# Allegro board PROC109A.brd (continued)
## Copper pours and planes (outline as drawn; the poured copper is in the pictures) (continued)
DGND on TOP: 50.8,-28.4 50.68,-28.52 50.68,-28.9 50.5,-29.07 49.77,-29.07 49.76,-29.08 46.97,-29.08 46.59,-28.7 46.59,-27.81 46.33,-27.56 45.83,-27.56 45.7,-27.69 45.7,-29.46 45.06,-29.46 44.68,-29.84 44.68,-30.86 44.57,-30.98 39.63,-30.98 39.37,-31.24 39.37,-33.91 39.62,-34.16 42.42,-34.16 42.86,-33.72 42.86,-31.94 43.31,-31.5 44.35,-31.5 44.35,-33.83 44.56,-34.04 45.49,-34.04 46.2,-33.32 53.39,-33.32 53.8,-32.92 53.8,-28.88 53.31,-28.4
DGND on TOP: 4.85,-54.79 4.85,-55.41 5.56,-56.12 7.63,-56.12 8.36,-56.85 10.19,-56.85 10.46,-56.57 10.46,-54.88 10.17,-54.58 5.05,-54.58
DGND on TOP: 74.68,-34.16 74.68,-34.71 75.19,-35.22 75.53,-35.22 76.48,-36.17 76.48,-36.53 76.65,-36.71 76.87,-36.71 76.96,-36.62 76.96,-34.88 76.24,-34.16
DGND on BOTTOM: 37.67,-36.4 37.92,-36.65 37.92,-37.29 37.67,-37.54 35.76,-37.54 35.66,-37.44 35.66,-36.47 35.74,-36.4
DGND on BOTTOM: 7.32,-56.64 10.72,-56.64 10.98,-56.38 10.98,-54.86 10.76,-54.64 7.34,-54.64 7.04,-54.94 7.04,-56.36
DGND on BOTTOM: 73.63,-40.61 75.9,-40.61 76.02,-40.49 76.02,-40.05 75.82,-39.85 73.62,-39.85 73.56,-39.91 73.56,-40.54
DGND on BOTTOM: 81.98,-47.97 83.24,-47.97 83.27,-48.01 83.27,-51.54 83.64,-51.91 83.64,-52.22 83.49,-52.37 81.89,-52.37 81.79,-52.27 81.79,-48.16
DGND on BOTTOM: 86.41,-49.79 86.32,-49.7 86.32,-48.44 86.58,-48.18 87.99,-48.18 88.14,-48.34 88.14,-49.64 87.99,-49.79
DGND on BOTTOM: 89.08,-45.69 89.49,-46.11 90.74,-46.11 90.86,-46.22 90.86,-46.61 90.7,-46.76 87.05,-46.76 86.9,-46.61 86.9,-45.83 87.03,-45.69
DGND on BOTTOM: 83.69,-42.11 83.69,-42.98 83.79,-43.08 84.96,-43.08 85.24,-42.8 85.24,-42.62 85.12,-42.49 85.12,-41.81 85.04,-41.73 84.73,-41.73 84.61,-41.86 84.61,-41.99 84.53,-42.06 83.74,-42.06
DGND on BOTTOM: 31.11,-60.93 33.78,-60.93 33.96,-60.76 33.96,-58.37 34.39,-57.94 38.33,-57.94 38.46,-57.81 38.46,-56.31 38.35,-56.21 36.37,-56.21 35.86,-55.7 35.86,-53.87 35.7,-53.71 31.63,-53.71 30.35,-52.43 24.76,-52.43 24.26,-52.93 24.26,-58.13 24.65,-58.52 28.7,-58.52
DGND on BOTTOM: 184.68,-10.16 184.68,-66.57 1.09,-66.57 1.09,-10.16 ; 123 cut-outs
DGND on BOTTOM: 86.12,-38.85 86.76,-38.21 89.05,-38.21 89.36,-37.9 89.36,-35.64 89.13,-35.41 86.13,-35.41 85.67,-35.86 85.67,-38.8 85.73,-38.85
DGND on BOTTOM: 78.03,-48.24 78.12,-48.34 78.12,-50.77 78.29,-50.94 78.29,-52.37 78.23,-52.43 76.45,-52.43 76.17,-52.15 76.17,-49.38 77.32,-48.24
DGND on BOTTOM: 81.74,-30.86 81.74,-32.49 81.79,-32.54 81.79,-34.26 82.19,-34.67 82.19,-36.01 80.9,-37.31 80.9,-37.67 80.98,-37.74 82.07,-37.74 82.19,-37.87 82.19,-38.46 82.37,-38.63 83.26,-38.63 83.36,-38.53 83.36,-36.86 83.19,-36.68 83.19,-35.63 82.96,-35.4 82.96,-32.89 83.79,-32.05 83.79,-31.04 83.52,-30.76 81.83,-30.76
DGND on BOTTOM: 78.55,-37.08 78.55,-34.81 78.44,-34.7 73.13,-34.7 72.85,-34.98 72.85,-37.04 72.92,-37.12 73.46,-37.12 73.71,-37.37 75.01,-37.37 75.31,-37.07 77.72,-37.07 77.88,-37.22 77.88,-39.57 78,-39.7 78.23,-39.7 78.36,-39.57 78.36,-37.26
DGND on BOTTOM: 86.33,-40.34 89.03,-40.34 89.23,-40.54 89.63,-40.54 89.74,-40.64 89.74,-41.1 89.73,-41.11 89.73,-41.72 89.48,-41.96 88.75,-41.96 88.44,-41.66 88.44,-41.35 88.29,-41.2 86.64,-41.2 86.31,-41.53 86.26,-41.53 85.78,-41.05 85.78,-40.89
DGND on BOTTOM: 11.39,-41.23 12.43,-41.23 12.84,-41.65 12.84,-43.69 12.97,-43.82 14.61,-43.82 14.78,-43.65 14.78,-43.28 14.66,-43.15 13.5,-43.15 13.39,-43.03 13.39,-40.69 13.21,-40.51 11.44,-40.51 11.24,-40.71 11.24,-41.09
DGND on BOTTOM: 127.95,-38.23 129.41,-38.23 129.67,-37.97 129.67,-34.22 129.48,-34.04 127.66,-34.04 127.52,-34.18 127.52,-34.76 127.15,-35.13 127.15,-35.51 127.75,-36.11 127.75,-38.03
DGND on L02_GND1: 184.22,-10.19 184.34,-12.55 184.34,-20.18 179.84,-20.18 179.84,-19.68 177.98,-17.81 174.08,-17.81 173.85,-18.05 173.85,-32.06 171.1,-34.82 168.29,-34.82 167.93,-35.17 167.93,-37.26 168.31,-37.64 176.06,-37.64 178.47,-35.23 184.33,-35.23 184.33,-41.81 180.27,-41.81 180.04,-41.58 180.04,-40.45 179.28,-39.69 174.67,-39.69 173.86,-40.5 173.86,-53.4 170.1,-57.16 170.1,-59.41 173.01,-59.41 173.93,-60.32 175.85,-60.32 177.9,-58.27 177.9,-57.47 178.42,-56.95 183.91,-56.95 183.91,-59.22 180.97,-62.15 180.97,-66.46 9.95,-66.46 8.84,-65.34 8.84,-58.3 6.16,-55.63 4.93,-55.63 4.37,-55.07 4.37,-52.6 4.95,-52.02 6.08,-52.02 7.16,-50.94 7.16,-48.97 6.91,-48.72 1.36,-48.72 1.11,-48.46 1.11,-10.19 1.11,-10.98 1.18,-11.08 1.29,-11.04 1.62,-10.66 2,-10.33 2.04,-10.27 2.03,-10.19
DGND on L03_SIG1: 184.68,-10.19 184.68,-66.57 1.09,-66.57 1.09,-10.19 ; 139 cut-outs
DGND on L05_GND2: 27.77,-66.53 27.48,-66.24 27.48,-59.13 27.23,-58.88 24.43,-58.88 23.63,-58.07 22.19,-58.07 20.75,-59.51 15.67,-59.51 15.39,-59.23 15.39,-58.72 15.04,-58.37 8.9,-58.37 6.74,-56.21 5.68,-56.21 4.11,-54.64 4.11,-52.27 4.37,-52.02 6.65,-52.02 7.16,-51.51 7.16,-48.97 6.91,-48.72 1.36,-48.72 1.15,-48.51 1.15,-11.35 2.23,-10.27 184.33,-10.27 184.33,-21.54 180.72,-21.54 179.87,-20.68 179.87,-19.7 177.98,-17.81 174.08,-17.81 173.85,-18.05 173.85,-32.06 171.1,-34.82 168.29,-34.82 167.93,-35.17 167.93,-37.26 168.31,-37.64 176.06,-37.64 178.51,-35.18 184.33,-35.18 184.33,-41.81 180.04,-41.81 180.04,-40.45 179.28,-39.69 174.67,-39.69 173.86,-40.5 173.86,-53.4 170.1,-57.16 170.1,-59.41 173.01,-59.41 173.93,-60.32 175.85,-60.32 177.9,-58.27 177.9,-57.47 178.47,-56.9 184.29,-56.9 184.29,-59.98 180.85,-63.42 180.85,-66.53 ; 2 cut-outs
VBUS_TYPEC on TOP: 19.64,-56.18 19.32,-55.86 19.32,-54.89 19.11,-54.68 17.66,-54.68 17.27,-55.07 17.27,-56 17.19,-56.08 15.31,-56.08 15.11,-55.88 15.11,-53.34 15.11,-53.34 15.11,-48.81 15.58,-48.34 21.03,-48.34 21.63,-48.95 21.63,-52.48 21.48,-52.63 21.48,-53.87 20.99,-54.37 20.99,-55.49 20.3,-56.18
VBUS_TYPEC on BOTTOM: 17.31,-54.23 17.31,-55.11 17.7,-55.5 19.3,-55.5 19.42,-55.38 19.42,-50.58 19.71,-50.29 20.9,-50.29 22.66,-52.05 22.66,-56.97 21.06,-58.57 15.39,-58.57 14.1,-57.28 14.1,-54.36 14.48,-53.97 17.05,-53.97
VBUS_TYPEC on L03_SIG1: 15.11,-52.71 15.12,-52.71 15.12,-49.86 16.63,-48.34 21.44,-48.34 21.83,-48.73 21.83,-55.78 21.43,-56.18 20.3,-56.18 20.3,-56.18 15.46,-56.18 15.11,-55.83
VBUS_XDS_USB on TOP: 4.8,-51.89 4.8,-52.43 4.93,-52.55 6.55,-52.55 7.51,-51.59 10.18,-51.59 10.36,-51.41 10.36,-50.6 10.08,-50.32 7.09,-50.32 6.39,-51.02 5.68,-51.02
VBUS_XDS_USB on BOTTOM: 12.21,-42.32 12.21,-41.91 12.09,-41.78 11.4,-41.78 11.3,-41.88 10.54,-41.88 10.44,-41.78 10.44,-40.59 10.31,-40.46 9.04,-40.46 8.91,-40.59 8.91,-42.39 8.89,-42.41 8.89,-44.23 10.57,-45.91 10.57,-49 9.17,-50.39 7.62,-50.39 7.37,-50.65 7.37,-51.46 7.55,-51.65 9.95,-51.65 11.95,-49.65 11.95,-45.56 9.7,-43.3 9.7,-42.87 9.99,-42.57 11.12,-42.57 11.38,-42.32
VCC3V3_TA on TOP: 5.34,-32.38 5.34,-31.89 5.84,-31.39 5.84,-30.77 5.63,-30.56 4.01,-30.56 3.53,-31.04 3.53,-32.89 3.72,-33.07 5.13,-33.07 5.49,-33.43 8.05,-33.43 8.26,-33.22 8.26,-32.89 8.05,-32.69 5.65,-32.69
VCC3V3_TA on TOP: 10.03,-19.28 11.25,-19.28 11.51,-19.53 11.51,-27.51 11.25,-27.76 10.03,-27.76 9.78,-27.51 9.78,-19.53
VCC3V3_TA on TOP: 29.69,-20.48 29.69,-21.92 29.16,-22.45 28.4,-22.45 28.19,-22.66 28.19,-23.29 28.27,-23.37 29.83,-23.37 30.14,-23.06 30.1,-23.06 30.46,-22.7 30.46,-22.57 30.56,-22.48 30.56,-21.76 31.32,-21 31.32,-20.52 31.16,-20.36 29.82,-20.36
VCC3V3_TA on TOP: 25.98,-22.61 25.98,-32.23 26.19,-32.44 26.59,-32.44 26.72,-32.31 26.72,-22.54 26.7,-22.52 26.07,-22.52
VCC3V3_TA on BOTTOM: 11.68,-19.47 11.68,-26.61 11.73,-26.66 12.4,-26.66 12.71,-26.35 12.71,-19.77 12.36,-19.42 11.73,-19.42
VCC3V3_TA on BOTTOM: 22.23,-20.19 22.23,-21.51 22.38,-21.67 22.96,-21.67 23.06,-21.56 23.06,-20.78 23.35,-20.49 24.69,-20.49 24.73,-20.45 24.73,-19.89 24.69,-19.85 23.08,-19.85 22.83,-20.09 22.33,-20.09
VCC3V3_TA on BOTTOM: 7.24,-48.89 7,-48.65 7,-46.98 6.38,-46.35 6.38,-44.58 6.17,-44.37 6.17,-40.76 5.31,-39.9 5.31,-38.79 5.56,-38.53 7.98,-38.53 8.13,-38.68 8.13,-40.87 8.13,-43.7 7.29,-44.53 7.29,-45.92 7.95,-46.58 9.44,-46.58 9.87,-47.02 9.87,-48.83 9.8,-48.89
VCC3V3_TA on L03_SIG1: 3.05,-28.9 3.05,-40.94 4.09,-41.99 6.71,-41.99 7.72,-40.97 7.72,-39.22 6.02,-37.52 6.02,-30.68 7.19,-29.51 7.57,-29.9 15.6,-29.9 17.46,-28.04 25.49,-28.04 27.15,-26.38 29.4,-26.38 30.35,-25.43 30.35,-21.36 28.52,-19.53 23.79,-19.53 20.6,-22.72 13.07,-22.72 12.4,-22.05 12.4,-19.35 11.89,-18.85 10.68,-18.85 6.83,-22.69 6.83,-25.11 ; 3 cut-outs
VCC3V3_XDS on TOP: 18.08,-36.8 17.5,-36.22 17.5,-28.21 18.04,-27.67 24.03,-27.67 24.03,-28.25 24.26,-28.25 24.67,-28.65 24.81,-28.65 24.81,-28.23 26.05,-28.23 26.05,-27.98 24.81,-27.98 24.81,-27.67 37.75,-27.67 38.35,-28.28 38.35,-36.55 38.1,-36.8 ; 4 cut-outs
VCC3V3_XDS on TOP: 14.17,-40 14.17,-43.23 15.65,-44.7 15.65,-46.66 15.7,-46.72 23.3,-46.72 24.12,-47.53 29.02,-47.53 29.71,-48.23 33.25,-48.23 35.64,-45.85 38.53,-45.85 39.5,-44.88 39.5,-39.85 37.97,-38.33 22.11,-38.33 20.43,-40 ; 3 cut-outs
VCC3V3_XDS on BOTTOM: 14.02,-42.2 14.66,-42.2 15.01,-42.54 16.51,-42.54 16.6,-42.63 17.24,-42.63 17.36,-42.51 17.36,-41.98 17.27,-41.88 16.22,-41.88 16.13,-41.79 16.13,-40 16.01,-39.88 14.1,-39.88 13.9,-40.07 13.9,-42.08
VCC3V3_XDS on BOTTOM: 35.8,-34.24 36.73,-34.24 36.91,-34.42 36.91,-35.48 36.65,-35.74 35.78,-35.74 35.66,-35.61 35.66,-34.37
VCC3V3_XDS on BOTTOM: 36.5,-44.29 36.34,-44.45 35.86,-44.45 35.53,-44.12 35.53,-41.83 35.71,-41.66 36.32,-41.66 36.5,-41.83
VCC3V3_XDS on BOTTOM: 25.16,-47.76 26.22,-47.76 26.42,-47.96 26.42,-48.51 26.16,-48.77 25.18,-48.77 25.04,-48.62 25.04,-47.89
VCC3V3_XDS on L03_SIG1: 13.64,-40.69 13.64,-45.54 15.19,-47.09 20.42,-47.09 20.83,-46.69 22.66,-46.69 23.62,-47.65 23.62,-52.38 26.34,-55.1 35.99,-55.1 36.49,-55.59 39.1,-55.59 40.17,-54.52 59.02,-54.52 59.34,-54.2 59.34,-50.4 58.96,-50.02 40.01,-50.02 38.38,-48.39 38.38,-41.96 38.23,-41.81 38.23,-35.38 36.93,-34.09 34.06,-34.09 33.13,-35.01 24.17,-35.01 21.39,-37.8 16.54,-37.8 ; 1 cut-out
VDD_1V1 on BOTTOM: 124.71,-44.25 124.71,-48.69 124.97,-48.95 126.53,-48.95 127.12,-48.35 127.12,-47.11 126.51,-46.5 126.51,-45.69 126.87,-45.33 126.87,-44.84 126.76,-44.73 126.09,-44.73 125.6,-44.25
VDD_1V1 on L04_PWR1: 136.5,-51.16 136.93,-51.6 139.03,-51.6 139.51,-51.12 139.51,-47.39 139.9,-46.99 144.76,-46.99 145.1,-46.65 145.1,-42.48 144.53,-41.91 139.36,-41.91 138.64,-41.19 138.64,-38.63 141.78,-35.49 141.78,-32.86 142.43,-32.22 144.39,-32.22 145.1,-31.5 145.1,-26.82 144.31,-26.03 133.76,-26.03 133.06,-26.73 133.06,-27.67 136.83,-31.44 136.83,-34.43 132.62,-38.64 125.6,-38.64 124.87,-39.37 124.87,-49.01 125.21,-49.35 130.57,-49.35 131.39,-48.53 131.39,-46.64 131.94,-46.1 135.8,-46.1 136.5,-46.8
VDD_1V8 on TOP: 66.55,-24.24 66.27,-24.51 65.19,-24.51 65.18,-24.5 64.2,-24.5 63.93,-24.23 63.93,-23.09 63.63,-22.78 63.12,-22.78 62.76,-22.43 62.76,-21.03 62.96,-20.83 66.32,-20.83 66.55,-21.06
VDD_1V8 on BOTTOM: 64.49,-21.86 64.49,-23.54 68.24,-27.29 71.29,-27.29 74.65,-30.65 74.65,-33.78 74.92,-34.05 78.49,-34.05 78.49,-32.06 78.23,-31.8 78.23,-30.91 68.85,-21.52 64.83,-21.52
VDD_1V8 on BOTTOM: 91.87,-41.4 93.57,-41.4 93.83,-41.66 93.83,-46.63 93.52,-46.94 91.62,-46.94 91.37,-46.69 91.37,-43.85 91.74,-43.48 91.74,-41.54
VDD_1V8 on BOTTOM: 68.12,-42.88 69.52,-42.88 69.77,-43.13 69.77,-49.48 69.45,-49.81 68.82,-49.81 68.34,-49.34 68.34,-44.16 67.87,-43.69 67.87,-43.13
VDD_1V8 on L04_PWR1: 91.36,-47.42 91.36,-43.92 87.73,-40.28 87.73,-36.53 86.18,-34.98 86.18,-34.8 86.11,-34.72 83.91,-34.72 82.08,-36.55 79.32,-36.55 76.69,-33.91 76.69,-32.38 77.18,-31.88 78.07,-31.88 78.28,-32.1 78.28,-33.19 80.44,-35.36 81.46,-35.36 83.24,-33.57 89.83,-33.57 90.84,-34.58 90.84,-38.89 93.62,-41.68 93.62,-50.47 93.24,-50.85 90.15,-50.85 87.99,-53.02 87.99,-54.48 87.38,-55.09 70.38,-55.09 67.21,-51.92 67.21,-48.83 69.88,-48.83 70.15,-49.1 70.15,-49.91 73.53,-53.29 85.7,-53.29 87.48,-51.51 87.48,-51.31
VDD_1V8_R on TOP: 61.83,-26.67 61.96,-26.8 66.37,-26.8 66.56,-26.6 66.56,-25.02 66.43,-24.89 63.65,-24.89 63.41,-25.13 63.41,-25.44 62.59,-26.26 61.85,-26.26 61.83,-26.29
VDD_2V5 on BOTTOM: 143.81,-46.48 145.11,-46.48 145.36,-46.74 145.36,-49.33 145.11,-49.58 143.81,-49.58 143.56,-49.33 143.56,-46.74
VDD_2V5 on BOTTOM: 143.87,-27.53 145.14,-27.53 145.39,-27.79 145.39,-30.66 145.14,-30.91 143.87,-30.91 143.61,-30.66 143.61,-27.79
VDD_2V5 on BOTTOM: 124.71,-37.97 124.71,-33.53 125.6,-33.53 126.09,-34.01 126.76,-34.01 126.87,-34.12 126.87,-34.5 126.51,-34.87 126.51,-35.78 127.1,-36.37 127.1,-37.82 126.57,-38.35 125.09,-38.35
VDD_2V5 on L03_SIG1: 144.17,-24.54 147.5,-24.54 148.13,-25.17 148.13,-49.23 147.5,-49.86 144.19,-49.86 143.37,-49.04 143.37,-40.61 142.26,-39.51 125.27,-39.51 124.84,-39.08 124.84,-36.04 124.99,-35.9 141.39,-35.9 143.69,-33.6 143.69,-25.02
VDD_CORE_0V85 on TOP: 60.41,-39.5 54.97,-39.5 54.77,-39.69 54.77,-43.62 54.85,-43.69 55.62,-43.69 55.94,-43.36 55.94,-43.22 56.17,-43 60.32,-43 60.57,-42.75 60.57,-39.65
VDD_CORE_0V85 on BOTTOM: 77.5,-39.16 73.57,-39.16 73.47,-39.06 73.47,-38.05 73.62,-37.9 74.97,-37.9 75.11,-38.04 77.57,-38.04 77.6,-38.07 77.6,-39.07
VDD_CORE_0V85 on BOTTOM: 79.12,-48.26 80.78,-48.26 80.95,-48.43 80.95,-51.84 81.15,-52.04 81.15,-52.27 81.01,-52.41 79.14,-52.41 78.96,-52.24 78.96,-48.42
VDD_CORE_0V85 on L03_SIG1: 78.82,-39.73 78.82,-47.73 85.65,-47.73 85.65,-39.73
VDD_CORE_0V85 on L04_PWR1: 84.2,-38.53 83.5,-37.82 54.89,-37.82 54.23,-38.48 54.23,-47.94 70.32,-47.94 74.41,-52.04 78.68,-52.04 78.82,-52.17 78.82,-52.67 81.57,-52.67 84.2,-50.04
VDD_CORE_0V85_R on TOP: 51.54,-39.75 51.8,-39.5 53.98,-39.5 54.25,-39.76 54.25,-42.54 54.15,-42.64 54.15,-43.43 54.1,-43.48 53,-43.48 52.94,-43.42 52.94,-42.54 52.68,-42.29 51.67,-42.29 51.54,-42.16
VDD_CORE_0V85_SW on TOP: 50.85,-39.62 49.64,-39.62 49.51,-39.75 49.51,-42.24 49.69,-42.42 50.86,-42.42 51,-42.28 51,-39.77
VDDA_1P8_USB0 on BOTTOM: 86.58,-42.27 86.58,-42.8 86.65,-42.88 88.33,-42.88 88.58,-43.12 90.87,-43.12 91.03,-42.97 91.03,-41.7 90.95,-41.62 90.12,-41.62 89.99,-41.75 89.99,-42.3 89.83,-42.46 88.42,-42.46 88.15,-42.19 86.66,-42.19
VDDA_1V8 on BOTTOM: 79.24,-32.95 79.24,-34.65 79.04,-34.85 79.04,-36.67 79.3,-36.93 80.21,-36.93 80.42,-36.73 80.42,-35.11 80.91,-34.62 80.91,-33 80.68,-32.77 79.43,-32.77
VDDA_PLL0 on BOTTOM: 90.72,-44.01 90.72,-45.46 90.57,-45.61 89.83,-45.61 89.3,-45.07 87.27,-45.07 87.16,-44.96 87.16,-44.57 87.26,-44.47 88.25,-44.47 88.82,-43.9 90.62,-43.9
VDDA_PLL1 on BOTTOM: 70.43,-47.57 70.43,-49.2 70.56,-49.33 71.65,-49.33 71.83,-49.15 71.83,-48.84 72.03,-48.64 75.06,-48.64 75.45,-48.24 75.45,-47.16 75.26,-46.96 74.7,-46.96 74.55,-47.12 74.55,-47.37 74.22,-47.7 72.19,-47.7 71.88,-47.4 70.61,-47.4
VDDA_PLL2 on BOTTOM: 70.36,-43.05 70.36,-44.34 70.48,-44.46 71.95,-44.46 72.52,-43.89 73.13,-43.89 73.23,-43.79 73.23,-43.13 73.03,-42.93 70.48,-42.93
VDDA_TEMP on BOTTOM: 70.48,-45.62 70.48,-46.69 70.66,-46.86 71.81,-46.86 72.47,-46.2 73.18,-46.2 73.3,-46.08 73.3,-45.62 72.82,-45.14 70.97,-45.14
VDDSHV_3V3 on BOTTOM: 73.62,-41.86 74.7,-41.86 74.96,-41.61 77.42,-41.61 77.57,-41.76 77.57,-42.65 77.1,-43.12 75.18,-43.12 74.93,-43.37 74.93,-44.02 75.08,-44.17 77.95,-44.17 78.64,-44.86 78.64,-45.52 78.56,-45.59 78.28,-45.59 78.05,-45.36 78.05,-45.16 77.9,-45.01 77.22,-45.01 76.81,-45.42 76.81,-48.01 76.68,-48.14 76.08,-48.14 75.98,-48.04 75.98,-46.87 74.26,-45.15 74.26,-43.56 73.53,-42.83 73.53,-41.94
VDDSHV_3V3 on BOTTOM: 83.74,-35.4 84.67,-35.4 84.84,-35.56 84.84,-38.99 84.58,-39.24 83.74,-39.24 83.67,-39.16 83.67,-35.48
VDDSHV_3V3 on BOTTOM: 84.25,-48.22 85.68,-48.22 85.89,-48.43 85.89,-50.2 85.85,-50.16 85.85,-52.34 85.61,-52.58 84.58,-52.58 84.12,-52.11 84.12,-48.35
VDDSHV_3V3 on BOTTOM: 83.31,-45.67 83.31,-46.84 84.35,-46.84 84.35,-45.67
VDDSHV_3V3 on L04_PWR1: 85.08,-47.34 84.71,-47.71 84.71,-50.32 83.73,-51.3 83.73,-51.99 84.4,-52.67 85.69,-52.67 87.02,-51.33 87.02,-51.08 90.5,-47.6 90.5,-43.38 87.19,-40.08 87.19,-36.53 86.09,-35.43 84.11,-35.43 83.59,-35.95 83.59,-37.27 83.67,-37.35 83.68,-37.35 84.41,-38.08 84.41,-40.53 84.1,-40.84 84.1,-44.98 85.08,-45.97
BP_3V3 on TOP: 101.12,-60.27 101.12,-62.28 105.28,-62.28 105.28,-60.27
BP_5V0 on TOP: 101.24,-59.66 101.24,-57.66 105.23,-57.66 105.23,-59.66
ETH1_EARTH on TOP: 174.18,-40.29 174.18,-53.59 170.39,-57.38 170.39,-59.09 173.09,-59.09 173.95,-59.95 175.66,-59.95 177.53,-58.09 177.53,-56.36 178.87,-55.02 184.46,-55.02 184.46,-43.97 180.47,-43.97 179.87,-43.36 179.87,-40.61 179.2,-39.95 174.51,-39.95
ETH1_EARTH on BOTTOM, L02_GND1, L03_SIG1, L04_PWR1, L05_GND2: 174.18,-40.29 174.18,-53.59 170.41,-57.36 170.41,-59.03 173.09,-59.03 174.02,-59.95 175.66,-59.95 177.53,-58.09 177.53,-56.36 178.87,-55.02 184.46,-55.02 184.46,-43.97 180.47,-43.97 179.87,-43.36 179.87,-40.61 179.2,-39.95 174.51,-39.95
ETH2_EARTH on TOP: 174.19,-18.03 174.08,-18.14 174.08,-32.34 171.33,-35.08 168.52,-35.08 168.13,-35.47 168.13,-36.99 168.47,-37.33 175.96,-37.33 179.19,-34.1 184.51,-34.1 184.51,-21.52 179.97,-21.52 179.87,-21.41 179.87,-19.91 177.98,-18.03
ETH2_EARTH on BOTTOM, L02_GND1, L03_SIG1, L04_PWR1, L05_GND2: 174.54,-17.68 174.08,-18.14 174.08,-32.34 171.33,-35.08 168.52,-35.08 168.14,-35.46 168.14,-36.99 168.47,-37.31 175.98,-37.31 179.19,-34.1 184.51,-34.1 184.51,-21.87 184.39,-22 180.45,-22 179.87,-21.41 179.87,-19.92 177.62,-17.68
USBC_SHIELD on TOP, L05_GND2: 13.11,-65.85 12.81,-65.55 12.81,-58.8 13.06,-58.55 14.97,-58.55 15.35,-58.93 15.35,-59.94 15.73,-60.32 21.32,-60.32 21.82,-59.82 21.82,-58.8 22.08,-58.55 23.98,-58.55 24.24,-58.29 24.24,-57.84 24.42,-57.66 27.03,-57.66 27.28,-57.91 27.28,-65.53 26.96,-65.85
USBC_SHIELD on BOTTOM: 13.1,-65.84 12.81,-65.55 12.81,-58.8 13.06,-58.55 14.97,-58.55 15.35,-58.93 15.35,-59.94 15.73,-60.32 21.32,-60.32 21.82,-59.82 21.82,-58.8 22.08,-58.55 23.6,-58.55 24.08,-59.03 24.08,-60.22 24.54,-60.68 27.42,-60.68 27.7,-60.96 27.7,-65.38 27.24,-65.84
USBC_SHIELD on L02_GND1: 13.1,-65.83 12.81,-65.54 12.81,-58.8 13.06,-58.55 13.86,-58.55 14.77,-59.46 14.77,-60.21 15.11,-60.55 21.51,-60.55 22.15,-59.92 22.15,-58.9 22.5,-58.55 23.98,-58.55 24.24,-58.29 24.24,-57.84 24.42,-57.66 27.03,-57.66 27.28,-57.91 27.28,-65.48 26.93,-65.83
USBC_SHIELD on L03_SIG1: 13.37,-66.1 12.81,-65.54 12.81,-58.8 13.06,-58.55 14.97,-58.55 15.35,-58.93 15.35,-59.94 15.73,-60.32 21.32,-60.32 21.82,-59.82 21.82,-58.8 22.08,-58.55 23.98,-58.55 24.24,-58.29 24.24,-57.84 24.42,-57.66 27.03,-57.66 27.28,-57.91 27.28,-65.54 26.73,-66.1
USBC_SHIELD on L04_PWR1: 13.11,-65.85 12.81,-65.55 12.81,-58.8 13.06,-58.55 14.97,-58.55 15.35,-58.93 15.35,-59.94 15.73,-60.32 21.32,-60.32 21.82,-59.82 21.82,-58.8 22.08,-58.55 23.98,-58.55 23.99,-58.54 26.61,-58.54 27.14,-59.07 27.14,-65.67 26.96,-65.85
VPP_1V8 on TOP: 53.24,-34.9 53.24,-35.99 53.44,-36.19 54.84,-36.19 55.12,-35.92 56.62,-35.92 56.72,-35.81 56.72,-34.32 56.44,-34.04 55.32,-34.04 54.61,-34.75 53.39,-34.75
VSYS_3V3 on TOP: 56.32,-29.57 54.44,-27.69 50.55,-27.69 50.27,-27.97 50.27,-28.26 50.08,-28.45 49.27,-28.45 49.2,-28.38 49.2,-24.21 49.87,-23.53 54.95,-23.53 57.71,-26.29 60.04,-26.29 60.18,-26.42 60.18,-26.8 60.05,-26.92 59.56,-26.92 59.44,-27.05 59.44,-29.29 59.16,-29.57
VSYS_3V3 on TOP: 95.96,-14.15 100.61,-14.15 100.86,-14.4 100.86,-16.46 100.68,-16.65 98.56,-16.65 98.42,-16.51 96.01,-16.51 95.71,-16.21 95.71,-14.4
VSYS_3V3 on TOP: 31.7,-21.64 31.7,-22.94 31.75,-22.99 32.26,-22.99 32.44,-23.16 34.85,-23.16 35.08,-22.94 35.08,-21.37 34.93,-21.22 32.12,-21.22
VSYS_3V3 on TOP: 8.81,-30.51 8.81,-31.24 9.35,-31.78 9.35,-32.92 9.49,-33.07 10.65,-33.07 10.82,-32.89 10.82,-30.78 10.54,-30.51
VSYS_3V3 on TOP: 139.57,-38 140.18,-38 140.39,-38.2 140.39,-40.97 140.25,-41.11 139.51,-41.11 139.32,-40.92 139.32,-38.25
VSYS_3V3 on TOP: 139.57,-18.95 140.18,-18.95 140.39,-19.15 140.39,-21.92 140.25,-22.06 139.62,-22.06 139.32,-21.75 139.32,-19.2
VSYS_3V3 on BOTTOM: 122.42,-45.14 122.42,-43.21 122.32,-43.1 121.38,-43.1 120.97,-42.69 116.42,-42.69 116.15,-42.95 116.15,-45.57 116.36,-45.77 121.79,-45.77
VSYS_3V3 on BOTTOM: 90.07,-51.03 90.07,-53.42 87.07,-53.42 86.52,-52.87 86.52,-50.52 86.61,-50.43 89.47,-50.43
VSYS_3V3 on BOTTOM: 35.69,-59.03 37.31,-59.03 37.57,-59.28 37.57,-62.53 37.31,-62.79 35.69,-62.79 35.43,-62.53 35.43,-59.28
VSYS_3V3 on BOTTOM: 122.42,-34.42 122.42,-31.19 122.2,-30.98 120.79,-30.98 119.79,-31.97 116.33,-31.97 116.13,-32.17 116.13,-34.82 116.36,-35.05 121.79,-35.05
VSYS_3V3 on L04_PWR1: 98.5,-56.34 98.5,-57.84 100.15,-57.84 100.15,-56.34
VSYS_3V3 on L04_PWR1: outline of 119 points within 1.11,-66.55 184.29,-10.21
VSYS_3V3_R on TOP: 45.94,-24.4 46.08,-24.26 48.38,-24.26 48.6,-24.47 48.6,-28.17 48.41,-28.35 47.26,-28.35 47.14,-28.24 47.14,-27.48 46.71,-27.05 46.07,-27.05 45.94,-26.92
VSYS_3V3_SW on TOP: 45.14,-24.38 43.92,-24.38 43.79,-24.51 43.79,-27 43.98,-27.18 45.15,-27.18 45.29,-27.04 45.29,-24.53
VSYS_5V0 on TOP: 32.62,-48.61 31.67,-49.56 31.67,-51.49 31.86,-51.67 32.81,-51.67 32.91,-51.57 33.25,-51.92 35.33,-51.92 36.6,-53.19 38.66,-53.19 39.14,-52.7 39.14,-49.01 38.74,-48.61
VSYS_5V0 on TOP: 120.83,-30.36 120.83,-32.56 120.93,-32.66 121.56,-32.66 121.84,-32.38 124.19,-32.38 125.46,-33.65 125.46,-52.28 127.38,-54.2 130.22,-54.2 136.06,-60.04 136.06,-62.12 136.47,-62.53 138.56,-62.53 138.73,-62.36 138.73,-60.2 129.55,-51.02 129.55,-31.3 128.43,-30.18 121.01,-30.18
VSYS_5V0 on TOP: 44.05,-29.74 44.05,-27.65 43.16,-26.77 43.16,-25.88 42.76,-25.47 39.76,-25.47 39.36,-25.87 39.36,-29.96 39.5,-30.1 43.69,-30.1
VSYS_5V0 on TOP: 45.34,-45.47 44.96,-45.08 44.96,-37.84 45.85,-36.95 45.85,-35.66 46.71,-34.8 51.63,-34.8 51.85,-35.01 51.85,-36.02 51.73,-36.14 48.65,-36.14 48.32,-36.48 48.32,-39.25 48.86,-39.8 48.86,-41.99 49.76,-42.89 49.76,-45.21 49.41,-45.21 49.15,-45.47
VSYS_5V0 on TOP: 99.47,-58.29 99.47,-59.66 100.84,-59.66 100.84,-58.29
VSYS_5V0 on L04_PWR1: 41.96,-59.61 37.44,-59.61 36.08,-58.26 36.08,-55.85 32.01,-51.78 32.01,-34.94 27.4,-30.33 27.23,-30.33 22.63,-25.73 12.42,-25.73 11.58,-24.89 11.58,-17.58 11.96,-17.2 23.88,-17.2 29.68,-22.99 41.64,-22.99 44.94,-26.29 44.94,-28.7 49.25,-33.02 51.16,-33.02 52.68,-34.54 52.68,-50.98 65.53,-50.98 70.15,-55.6 88.04,-55.6 88.19,-55.75 149.42,-55.75 153.25,-51.92 160.1,-51.92 161.72,-50.29 164.87,-50.29 165.56,-50.98 165.56,-57.81 167.09,-59.34 167.11,-59.34 170.36,-62.58 170.36,-65.84 169.77,-66.42 73.32,-66.42 67.16,-60.26 42.61,-60.26
VUSB_5V0 on TOP: 22.23,-51.89 22.23,-48.38 22.45,-48.16 29.21,-48.16 29.98,-48.93 29.98,-50.5 30.28,-50.79 30.28,-51.61 30.1,-51.79 29.06,-51.79 28.82,-52.03 27.88,-52.03 27.43,-52.48 22.81,-52.48
VUSB_5V0 on BOTTOM: 1.4,-46.91 1.4,-48.06 1.69,-48.36 5.99,-48.36 6.21,-48.14 6.21,-46.88 6.1,-46.76 4.68,-46.76 4.53,-46.92 3.11,-46.92 2.86,-46.66 1.64,-46.66
XDS_SHIELD on TOP, L04_PWR1, L05_GND2: 1.78,-60.12 1.11,-59.45 1.11,-48.83 1.35,-48.59 6.65,-48.59 6.96,-48.9 6.96,-49.96 6.27,-50.65 4.01,-50.65 3.56,-51.1 3.56,-55.97 4.15,-56.57 6.55,-56.57 7.67,-57.68 10.64,-57.68 10.95,-57.99 10.95,-59.76 10.58,-60.12
XDS_SHIELD on BOTTOM: 1.58,-60.35 1.11,-59.87 1.11,-49.34 1.42,-49.02 6.42,-49.02 6.83,-49.43 6.83,-51.03 6.09,-51.77 4.26,-51.77 3.78,-52.24 3.78,-56.13 4.29,-56.64 6.27,-56.64 7.14,-57.51 7.14,-58.06 8.03,-58.95 11.02,-58.95 11.2,-59.13 11.2,-60.14 10.99,-60.35
XDS_SHIELD on L02_GND1: 1.78,-60.12 1.11,-59.45 1.11,-48.83 1.35,-48.59 6.65,-48.59 6.96,-48.9 6.96,-49.96 6.27,-50.65 4.01,-50.65 3.56,-51.1 3.56,-55.97 4.15,-56.57 6.55,-56.57 8.15,-58.17 8.15,-59.74 7.77,-60.12
XDS_SHIELD on L03_SIG1: 1.78,-60.12 1.11,-59.45 1.11,-48.83 1.35,-48.59 6.65,-48.59 6.96,-48.9 6.96,-49.96 6.27,-50.65 4.01,-50.65 3.56,-51.1 3.56,-55.97 4.15,-56.57 6.55,-56.57 7.67,-57.68 8.23,-57.68 8.43,-57.89 8.43,-59.79 8.1,-60.12

Small or netless copper shapes (teardrops, artwork), in the pictures only: 264 on L03_SIG1, 491 on TOP, 373 on BOTTOM, 5 on L04_PWR1, 2 on L05_GND2

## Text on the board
Ref Des/Assembly Bottom: BOTTOM ASSEMBLY
Ref Des/Silkscreen Bottom: B | A | C | J1 | J3 | J4 | J2 | J5 | J8 | J7 | J6 | Development Kit | LP-AM243 | www.ti.com/launchpad | TEST AUTOMATION | FOR EVALUATION ONLY; | NOT FCC APPROVED FOR RESALE
User.Comments: BOARD NAME: | AM243x LP EVM | REV: | DATE: 15-03-2023 | A | DESCRIPTION: | SHEET    OF 13 | PROC109A | SCALE: 1 | TEXAS INSTRUMENTS
Ref Des/Assembly Top: TOP ASSEMBLY
Ref Des/Silkscreen Top: XDS110,MAIN UART0 | A | MCU PORZ | BOOT MODE SEL | VBUS_TYPEC | MCU RESETZ | BRD PWR IN | VSYS_5V0 ON | VSYS_3V3 ON | VDDCORE_0V85 ON | VCC3V3_XDS | SOC_RESET_REQZ | VSYS_5V0 | VSYS_3V3 | MCU_RESETz | USER_INTn | VDD_1V8 | J1 | J3 | J4 | J2 | USER INTN | SOC_RESETSTATz | PORz_OUT | FSI | VDD_1V1 | VDD_2V5 | J8 | J6 | J5 | J7 | eQEP1 | MAIN UART1 | MCU UART0 | eQEP2 | MCAN0 | IND LEDS | PWR ERR | MCU_PORz | 21 | 1 | 20 | 40 | 5V0 | 3V3 | GND | 2 | 39 | 19 | 3 | 18 | 38 | 23 | 4 | 17 | 37 | 24 | 5 | 16 | 36 | 25 | 6 | 15 | 35 | 26 | 7 | 14 | 34 | 27 | 8 | 13 | 33 | 28 | VDD_CORE_0V85 | 9 | 32 | 12 | 29 | SoC_RESET_REQz | 11 | 30 | 10 | 31 | OSPI0 CLK | MCU_SAFTY_ERRz | MCU RESETSTATz | 60 | 80 | 61 | 41 | 42 | 79 | 59 | 43 | 78 | 58 | 63 | 44 | 77 | 57 | 64 | 45 | 76 | 56 | 65 | 46 | 75 | 55 | 66 | 47 | 74 | 54 | 67 | 48 | 73 | 53 | 68 | 49 | 72 | 52 | 69 | 51 | 50 | 70 | 71 | IND LED GREEN | PRG/CPSW RGMII2 | PRG/CPSW RGMII1 | IND LED RED | IND LED BCLR | ASSY | OPN#: LP-AM243 | PCB#:PROC109A | SL#
PAGE_OUTLINE: 17. | FOR DETAILED STACK-UP, PROC109_STACK_UP.pdf SHALL BE REFERRED | ENSURE THAT UL REGISTERED E-FILE NUMBER SHALL BE PRINTED ON PCB SILKSCREEN. | REVIEWED BY | APPROVED BY | LAYOUT BY | SIGNATURES | PA | ZA | AMB | 19-11-21 | DATE | SIZE | SCALE: | D | NONE | SHEET 1 OF 13 | PROC109E3 | Rev | TEXAS INSTRUMENTS | E3 | AM243x LP EVM
User.10: R178 | R186 | R189 | R197 | R209 | R171 | C146 | C155 | R182 | R187 | Q8 | Y1 | R196 | R202 | R212 | R219 | R222 | R231 | C114 | R246 | D7 | U27 | C120 | C132 | D6 | R176 | R195 | C85 | D8 | R256 | Q7 | R191 | R170 | C240 | C268 | C129 | C151 | C180 | C191 | C192 | C184 | C135 | C144 | C163 | J2 | J1 | C134 | C141 | C203 | C133 | C140 | C145 | Q16 | R255 | R262 | C260 | C232 | U42 | C161 | FB6 | FB8 | R234 | FB9 | FB3 | R240 | R244 | C193 | C259 | R271 | C94 | C194 | FB2 | C234 | C244 | C250 | C255 | C227 | C126 | C239 | C247 | C251 | C254 | R183 | C116 | C235 | C245 | C249 | C253 | R208 | C237 | C246 | R261 | C206 | FB4 | R206 | FB7 | FB5 | U30 | C209 | C166 | R250 | J6 | J5 | U33 | U39 | R248 | R233 | U29 | C125 | C130 | C222 | R218 | R221 | R230 | R254 | R260 | C98 | C97 | C228 | C93 | C207 | C221 | R242 | C258 | R266 | C86 | C100 | C217 | C231 | C96 | C84 | C159 | C152 | U46 | C119 | R236 | C92 | C95 | C99 | R225 | C197 | C230 | C216 | C107 | C238 | R241 | R245 | R259 | R263 | R276 | Q14 | Q15 | Q10 | Q11 | Q12 | Q13 | R270 | C257 | Q6 | C83 | C261 | C264 | C115 | C127 | Q5 | C195 | C89 | Q4 | Q9 | R200 | R253 | C101 | C252 | U38 | R188 | U26 | U37 | U45 | U28 | U36 | C153 | R287 | C224 | FB1 | U31 | R286 | U40 | C248 | U32 | C87 | U34 | U43 | U35 | U44 | C202 | C160 | C158 | C165 | WHEN ACTUATOR IS OPENED | R251 | J15 | C226 | C243 | C263 | D5 | C79 | C170 | R211 | C131 | R249 | C208 | C91 | C182 | L3 | C154 | C181 | R201 | R175 | R177 | C266 | C242 | C104 | C105 | C102 | C88 | C121 | C262 | C128 | R235 | R224 | C171 | C169 | C189 | C168 | C167 | C210 | C162 | C201 | C214 | C148 | C188 | C200 | C215 | C172 | C147 | C187 | C199 | C175 | C212 | C186 | C173 | C211 | C185 | C150 | C196 | C149 | C213 | C179 | R238 | C108 | R237 | C110 | C117 | C118 | C225 | C241 | C142 | C236 | C136 | R181 | C139 | C138 | R180 | C223 | C137 | R179 | C233 | R239 | R217 | C204 | C156 | R216 | R194 | R207 | R193 | R215 | R192 | R214 | R205 | R213 | R204 | C90 | R203 | R190 | C124 | C220 | C123 | C219 | C122 | C218 | C111 | C183 | C229 | R232 | R247 | R269 | R268 | R229 | R228 | R267 | R184 | C113 | C256 | R185 | C270 | R227 | R275 | R226 | R265 | R264 | C269 | R274 | R281 | R280 | R273 | R257 | R252 | R279 | R272 | C112 | R223 | R220 | R243 | R278 | R277 | R173 | C267 | R210 | R258 | C265 | C164 | R172 | R167 | R166 | R285 | R169 | R284 | R165 | R174 | R283 | R168 | R282 | U41 | C82 | C81 | R199 | C80 | R198 | C190 | C174 | C143 | C198 | C178 | C177 | C176 | C157 | C109 | C103 | C106 | C205 | REV # | SCALE:NONE | SIZE | FILE NAME: | DESCRIPTION | REVISIONS | CCN # | DRAWING NO. | DDMMYY | DATE | OF | REV | AM243x LP EVM ASSEMBLY BOTTOM REV.E1 | SHEET | 02 | C | FY10XXXX5200X0X | *
User.14: LED102 | LED101 | J1 | J5 | J7 | S1 | J3 | C3 | C7 | R1 | C1 | R7 | R5 | Q2 | R2 | Q1 | R3 | R4 | MSP1 | C10 | C8 | TP110 | L1 | C4 | S3 | J4 | JP102 | S2 | J6 | J2 | C11 | C6 | C5 | C12 | C2 | J102 | J8 | C13 | R6 | J101
User.42: 06 | EDGE COUPLED STRIPLINE | EDGE COUPLED MICROSTRIP | L3 | L1,L6 | 4.75 | 5.3 | NA | 50 | L2 | L2,L5
User.45: BOARD NAME: | AM243x LP EVM | REV: | DATE: 15-09-21 | E3 | DESCRIPTION: | SHEET    OF 13 | PROC109 | SCALE: 1 | TEXAS INSTRUMENTS | FIGURE | SIZE | 8.0 | 16.0 | 36.0 | 40.0 | 44.0 | 46.0 | 66.0 | 32.0 | 126.0 | 48.0x22.0 | 48.0x24.0 | 68.0x34.0 | DRILL CHART: TOP to BOTTOM | ALL UNITS ARE IN MILS | TOLERANCE | +3.0/-3.0 | +2.0/-2.0 | PLATED | NON-PLATED | QTY | 1494 | 14 | 20 | 43 | 80 | 4 | 8 | 92 | 2
